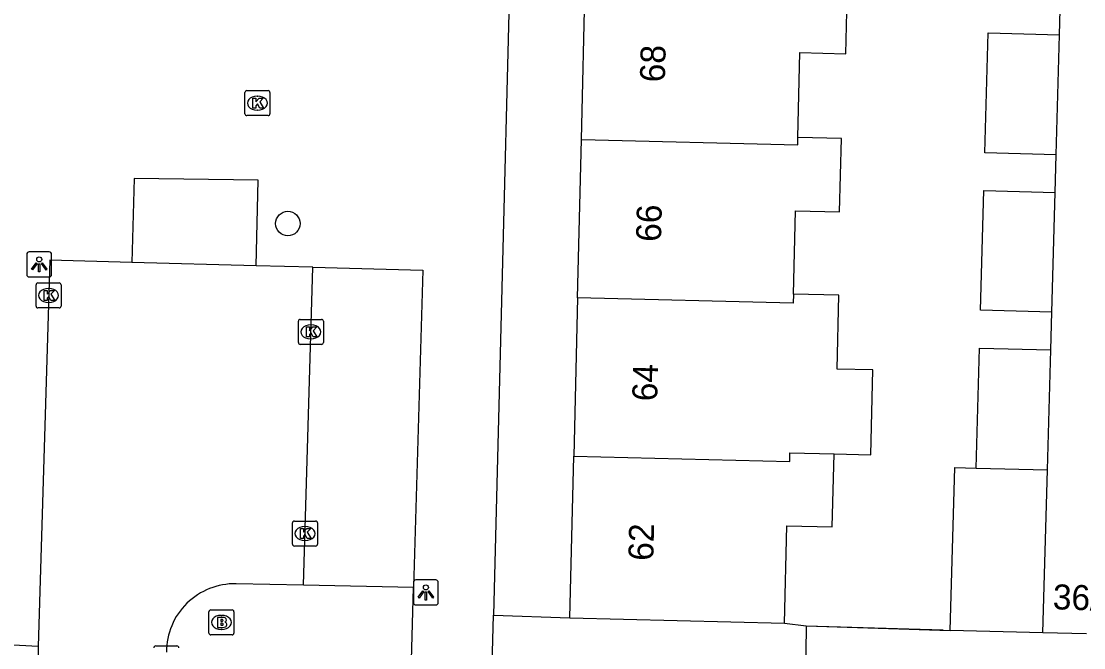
# Model space of a CAD drawing. Extents: x 162082 to 163393, y 388091 to 388632.
# Drawn here: x 162447.32 to 162489.83, y 388250.18 to 388275.23 of the extents above; entities that cross this region are included whole.
import ezdxf

# ---------------------------------------------------------------- set-up
doc = ezdxf.new("R2010")
doc.units = 0
for name, color, linetype in [('IMGEO_Boom', 7, 'Continuous'), ('IMGEO_Brandkraan', 7, 'Continuous'), ('IMGEO_Kolk', 7, 'Continuous'), ('IMGEO_Lichtpunt', 7, 'Continuous'), ('IMGEO_Muur', 7, 'Continuous'), ('IMGEO_Pand', 7, 'Continuous'), ('IMGEO_Pand_nummerreeks', 7, 'Continuous'), ('IMGEO_Rijbaan_lokaal_open', 7, 'Continuous'), ('IMGEO_Voetpad_open', 7, 'Continuous')]:
    doc.layers.add(name, color=color, linetype=linetype)

msp = doc.modelspace()

# ---------------------------------------------------------------- linework, layer by layer
at = {"layer": 'IMGEO_Boom'}
msp.add_circle((162457.99, 388267.141), 0.489, dxfattribs=at)
at = {"layer": 'IMGEO_Brandkraan'}
for p, q in [((162454.832, 388250.766), (162454.832, 388251.618)), ((162454.907, 388251.692), (162455.759, 388251.692)), ((162455.32, 388251.472), (162455.345, 388251.472)), ((162455.833, 388251.618), (162455.833, 388250.766)), ((162455.343, 388250.912), (162455.318, 388250.912)), ((162455.759, 388250.692), (162454.907, 388250.692))]:
    msp.add_line(p, q, dxfattribs=at)
for points in [[(162454.832, 388250.766), (162454.832, 388251.618)], [(162454.907, 388251.692), (162455.759, 388251.692)], [(162455.18, 388251.392), (162455.18, 388250.992), (162455.393, 388250.992)], [(162455.411, 388251.392), (162455.18, 388251.392)], [(162455.833, 388251.618), (162455.833, 388250.766)], [(162455.359, 388251.311), (162455.305, 388251.311), (162455.305, 388251.235)], [(162455.305, 388251.235), (162455.358, 388251.235)], [(162455.367, 388251.159), (162455.305, 388251.159), (162455.305, 388251.078)], [(162455.305, 388251.078), (162455.367, 388251.078)], [(162455.759, 388250.692), (162454.907, 388250.692)]]:
    msp.add_lwpolyline(points, dxfattribs=at)
for centre, radius, start, end in [((162454.909, 388251.616), 0.0765, 91.552, 178.448), ((162454.909, 388251.616), 0.0765, 91.552, 178.448), ((162455.415, 388251.247), 0.145, 59.4692, 91.5367), ((162455.44, 388251.294), 0.0922, 285.5137, 58.1501), ((162455.757, 388251.616), 0.0765, 1.552, 88.448), ((162455.757, 388251.616), 0.0765, 1.552, 88.448), ((162455.36, 388251.273), 0.0379, 267.8285, 90.9355), ((162455.368, 388251.118), 0.0404, 269.8759, 90.5077), ((162455.399, 388251.243), 0.251, 268.6676, 293.5347), ((162455.445, 388251.102), 0.105, 301.3115, 78.989), ((162454.909, 388250.768), 0.0765, 181.552, 268.448), ((162454.909, 388250.768), 0.0765, 181.552, 268.448), ((162455.757, 388250.768), 0.0765, 271.552, 358.448), ((162455.757, 388250.768), 0.0765, 271.552, 358.448)]:
    msp.add_arc(centre, radius, start, end, dxfattribs=at)
for centre, major_axis, ratio, start_param, end_param in [((162455.319, 388251.192), (-0.387, 0.002), 0.722429, 4.712389, 7.853982), ((162455.344, 388251.192), (-0.39, 0.002), 0.717154, 1.570796, 4.712389)]:
    msp.add_ellipse(centre, major_axis=major_axis, ratio=ratio, start_param=start_param, end_param=end_param, dxfattribs=at)
at = {"layer": 'IMGEO_Kolk'}
for p, q in [((162456.271, 388271.532), (162456.271, 388272.384)), ((162456.346, 388272.458), (162457.198, 388272.458)), ((162456.759, 388272.238), (162456.784, 388272.238)), ((162457.272, 388272.384), (162457.272, 388271.532)), ((162457.198, 388271.458), (162456.346, 388271.458)), ((162456.782, 388271.678), (162456.757, 388271.678)), ((162447.917, 388263.84), (162447.917, 388264.692)), ((162447.992, 388264.766), (162448.844, 388264.766)), ((162448.405, 388264.546), (162448.43, 388264.546)), ((162448.918, 388264.692), (162448.918, 388263.84)), ((162448.844, 388263.766), (162447.992, 388263.766)), ((162448.428, 388263.986), (162448.403, 388263.986)), ((162458.41, 388262.382), (162458.41, 388263.234)), ((162458.485, 388263.308), (162459.337, 388263.308)), ((162459.411, 388263.234), (162459.411, 388262.382)), ((162458.898, 388263.088), (162458.923, 388263.088)), ((162458.921, 388262.528), (162458.896, 388262.528)), ((162459.337, 388262.308), (162458.485, 388262.308)), ((162458.175, 388254.318), (162458.175, 388255.17)), ((162458.25, 388255.244), (162459.102, 388255.244)), ((162459.176, 388255.17), (162459.176, 388254.318)), ((162458.663, 388255.024), (162458.688, 388255.024)), ((162458.686, 388254.464), (162458.661, 388254.464)), ((162459.102, 388254.244), (162458.25, 388254.244)), ((162452.703, 388250.251), (162453.555, 388250.251))]:
    msp.add_line(p, q, dxfattribs=at)
for points in [[(162456.271, 388271.532), (162456.271, 388272.384)], [(162456.346, 388272.458), (162457.198, 388272.458)], [(162456.592, 388272.158), (162456.715, 388272.158), (162456.715, 388272.007), (162456.845, 388272.158), (162457.009, 388272.158), (162456.863, 388272.007), (162457.016, 388271.758), (162456.864, 388271.758), (162456.779, 388271.922), (162456.715, 388271.855), (162456.715, 388271.758), (162456.592, 388271.758), (162456.592, 388272.158)], [(162457.272, 388272.384), (162457.272, 388271.532)], [(162457.198, 388271.458), (162456.346, 388271.458)], [(162447.917, 388263.84), (162447.917, 388264.692)], [(162447.992, 388264.766), (162448.844, 388264.766)], [(162448.918, 388264.692), (162448.918, 388263.84)], [(162448.238, 388264.466), (162448.361, 388264.466), (162448.361, 388264.315), (162448.491, 388264.466), (162448.655, 388264.466), (162448.509, 388264.315), (162448.662, 388264.066), (162448.51, 388264.066), (162448.425, 388264.23), (162448.361, 388264.163), (162448.361, 388264.066), (162448.238, 388264.066), (162448.238, 388264.466)], [(162448.844, 388263.766), (162447.992, 388263.766)], [(162458.41, 388262.382), (162458.41, 388263.234)], [(162458.485, 388263.308), (162459.337, 388263.308)], [(162459.411, 388263.234), (162459.411, 388262.382)], [(162458.731, 388263.008), (162458.854, 388263.008), (162458.854, 388262.857), (162458.984, 388263.008), (162459.148, 388263.008), (162459.002, 388262.857), (162459.155, 388262.608), (162459.003, 388262.608), (162458.918, 388262.772), (162458.854, 388262.705), (162458.854, 388262.608), (162458.731, 388262.608), (162458.731, 388263.008)], [(162459.337, 388262.308), (162458.485, 388262.308)], [(162458.175, 388254.318), (162458.175, 388255.17)], [(162458.25, 388255.244), (162459.102, 388255.244)], [(162459.176, 388255.17), (162459.176, 388254.318)], [(162458.496, 388254.944), (162458.619, 388254.944), (162458.619, 388254.793), (162458.749, 388254.944), (162458.913, 388254.944), (162458.767, 388254.793), (162458.92, 388254.544), (162458.768, 388254.544), (162458.683, 388254.708), (162458.619, 388254.641), (162458.619, 388254.544), (162458.496, 388254.544), (162458.496, 388254.944)], [(162459.102, 388254.244), (162458.25, 388254.244)], [(162452.703, 388250.251), (162453.555, 388250.251)]]:
    msp.add_lwpolyline(points, dxfattribs=at)
for centre, start, end in [((162456.348, 388272.382), 91.552, 178.448), ((162456.348, 388272.382), 91.552, 178.448), ((162457.196, 388272.382), 1.552, 88.448), ((162457.196, 388272.382), 1.552, 88.448), ((162456.348, 388271.534), 181.552, 268.448), ((162456.348, 388271.534), 181.552, 268.448), ((162457.196, 388271.534), 271.552, 358.448), ((162457.196, 388271.534), 271.552, 358.448), ((162447.994, 388264.69), 91.552, 178.448), ((162447.994, 388264.69), 91.552, 178.448), ((162448.842, 388264.69), 1.552, 88.448), ((162448.842, 388264.69), 1.552, 88.448), ((162447.994, 388263.842), 181.552, 268.448), ((162447.994, 388263.842), 181.552, 268.448), ((162448.842, 388263.842), 271.552, 358.448), ((162448.842, 388263.842), 271.552, 358.448), ((162458.487, 388263.232), 91.552, 178.448), ((162458.487, 388263.232), 91.552, 178.448), ((162459.335, 388263.232), 1.552, 88.448), ((162459.335, 388263.232), 1.552, 88.448), ((162458.487, 388262.384), 181.552, 268.448), ((162458.487, 388262.384), 181.552, 268.448), ((162459.335, 388262.384), 271.552, 358.448), ((162459.335, 388262.384), 271.552, 358.448), ((162458.252, 388255.168), 91.552, 178.448), ((162458.252, 388255.168), 91.552, 178.448), ((162459.1, 388255.168), 1.552, 88.448), ((162459.1, 388255.168), 1.552, 88.448), ((162458.252, 388254.32), 181.552, 268.448), ((162458.252, 388254.32), 181.552, 268.448), ((162459.1, 388254.32), 271.552, 358.448), ((162459.1, 388254.32), 271.552, 358.448), ((162452.705, 388250.175), 91.552, 178.448), ((162452.705, 388250.175), 91.552, 178.448), ((162453.553, 388250.175), 1.552, 88.448), ((162453.553, 388250.175), 1.552, 88.448)]:
    msp.add_arc(centre, 0.0765, start, end, dxfattribs=at)
for centre, major_axis, ratio, start_param, end_param in [((162456.758, 388271.958), (-0.387, 0.002), 0.722429, 4.712389, 7.853982), ((162456.783, 388271.958), (-0.39, 0.002), 0.717154, 1.570796, 4.712389), ((162448.404, 388264.266), (-0.387, 0.002), 0.722429, 4.712389, 7.853982), ((162448.429, 388264.266), (-0.39, 0.002), 0.717154, 1.570796, 4.712389), ((162458.897, 388262.808), (-0.387, 0.002), 0.722429, 4.712389, 7.853982), ((162458.922, 388262.808), (-0.39, 0.002), 0.717154, 1.570796, 4.712389), ((162458.662, 388254.744), (-0.387, 0.002), 0.722429, 4.712389, 7.853982), ((162458.687, 388254.744), (-0.39, 0.002), 0.717154, 1.570796, 4.712389)]:
    msp.add_ellipse(centre, major_axis=major_axis, ratio=ratio, start_param=start_param, end_param=end_param, dxfattribs=at)
at = {"layer": 'IMGEO_Lichtpunt'}
for p, q in [((162447.543, 388265.91), (162447.543, 388265.103)), ((162447.543, 388265.91), (162447.543, 388265.103)), ((162448.445, 388266.005), (162447.637, 388266.005)), ((162448.445, 388266.005), (162447.637, 388266.005)), ((162448.539, 388265.103), (162448.539, 388265.91)), ((162448.539, 388265.103), (162448.539, 388265.91)), ((162447.637, 388265.009), (162448.445, 388265.009)), ((162447.637, 388265.009), (162448.445, 388265.009)), ((162463.013, 388252.792), (162463.013, 388251.985)), ((162463.013, 388252.792), (162463.013, 388251.985)), ((162463.915, 388252.887), (162463.107, 388252.887)), ((162463.915, 388252.887), (162463.107, 388252.887)), ((162464.009, 388251.985), (162464.009, 388252.792)), ((162464.009, 388251.985), (162464.009, 388252.792)), ((162463.107, 388251.891), (162463.915, 388251.891)), ((162463.107, 388251.891), (162463.915, 388251.891))]:
    msp.add_line(p, q, dxfattribs=at)
for points in [[(162447.917, 388265.574), (162447.956, 388265.546), (162447.768, 388265.284), (162447.73, 388265.311), (162447.917, 388265.574)], [(162448.019, 388265.526), (162448.066, 388265.526), (162448.066, 388265.204), (162448.019, 388265.204), (162448.019, 388265.526)], [(162448.129, 388265.546), (162448.167, 388265.573), (162448.354, 388265.311), (162448.315, 388265.283), (162448.129, 388265.546)], [(162463.387, 388252.456), (162463.426, 388252.428), (162463.238, 388252.166), (162463.2, 388252.193), (162463.387, 388252.456)], [(162463.489, 388252.408), (162463.536, 388252.408), (162463.536, 388252.086), (162463.489, 388252.086), (162463.489, 388252.408)], [(162463.599, 388252.428), (162463.637, 388252.455), (162463.824, 388252.193), (162463.785, 388252.165), (162463.599, 388252.428)]]:
    msp.add_lwpolyline(points, dxfattribs=at)
for centre in [(162448.042, 388265.708), (162463.512, 388252.59)]:
    msp.add_circle(centre, 0.0994, dxfattribs=at)
for centre, start, end in [((162447.637, 388265.91), 90, 180), ((162447.637, 388265.91), 90, 180), ((162448.445, 388265.91), 0, 90), ((162448.445, 388265.91), 0, 90), ((162447.637, 388265.103), 180, 270), ((162447.637, 388265.103), 180, 270), ((162448.445, 388265.103), 270, 0), ((162448.445, 388265.103), 270, 360), ((162463.107, 388252.792), 90, 180), ((162463.107, 388252.792), 90, 180), ((162463.915, 388252.792), 0, 90), ((162463.915, 388252.792), 0, 90), ((162463.107, 388251.985), 180, 270), ((162463.107, 388251.985), 180, 270), ((162463.915, 388251.985), 270, 0), ((162463.915, 388251.985), 270, 360)]:
    msp.add_arc(centre, 0.0946, start, end, dxfattribs=at)
at = {"layer": 'IMGEO_Muur'}
for points in [[(162477.859, 388251.16), (162478.732, 388251.049)], [(162478.732, 388251.049), (162484.208, 388250.888)]]:
    msp.add_lwpolyline(points, dxfattribs=at)
at = {"layer": 'IMGEO_Pand'}
for points in [[(162469.737, 388270.498), (162469.89, 388276.829)], [(162478.396, 388270.582), (162478.478, 388273.976), (162480.318, 388273.931), (162480.386, 388276.746), (162478.573, 388276.789)], [(162488.725, 388269.889), (162485.876, 388269.967), (162486.008, 388274.768), (162488.857, 388274.689)], [(162488.725, 388269.889), (162488.857, 388274.689)], [(162469.584, 388264.166), (162469.737, 388270.498)], [(162469.737, 388270.498), (162478.389, 388270.288), (162478.396, 388270.582)], [(162478.221, 388264.316), (162478.301, 388267.654), (162480.064, 388267.611), (162480.135, 388270.54), (162478.396, 388270.582)], [(162488.552, 388263.594), (162485.703, 388263.672), (162485.835, 388268.46), (162488.683, 388268.382)], [(162488.552, 388263.594), (162488.683, 388268.382)], [(162469.584, 388264.166), (162469.431, 388257.835)], [(162478.221, 388264.316), (162478.212, 388263.957), (162469.584, 388264.166)], [(162479.841, 388257.931), (162481.31, 388257.896), (162481.392, 388261.288), (162479.967, 388261.323), (162480.038, 388264.272), (162478.221, 388264.316)], [(162485.529, 388257.362), (162485.661, 388262.164), (162488.51, 388262.086)], [(162488.378, 388257.291), (162488.51, 388262.086)], [(162469.275, 388251.368), (162469.431, 388257.835)], [(162469.431, 388257.835), (162478.07, 388257.626), (162478.078, 388257.973), (162479.841, 388257.931)], [(162477.859, 388251.16), (162477.953, 388255.051), (162479.771, 388255.007), (162479.841, 388257.931)], [(162484.49, 388250.866), (162484.669, 388257.384), (162485.529, 388257.362)], [(162485.529, 388257.362), (162488.378, 388257.291)], [(162488.199, 388250.773), (162488.378, 388257.291)], [(162469.275, 388251.368), (162477.859, 388251.16)], [(162488.199, 388250.773), (162484.49, 388250.866)]]:
    msp.add_lwpolyline(points, dxfattribs=at)
at = {"layer": 'IMGEO_Rijbaan_lokaal_open'}
for points in [[(162451.743, 388265.583), (162448.461, 388265.67), (162448.003, 388250.23)], [(162456.719, 388265.451), (162451.743, 388265.583)], [(162458.985, 388265.391), (162456.719, 388265.451)], [(162458.615, 388252.676), (162458.985, 388265.391)], [(162458.615, 388252.676), (162455.92, 388252.734)], [(162478.732, 388251.049), (162478.71, 388250), (162478.694, 388249.226)], [(162478.732, 388251.049), (162484.49, 388250.866)], [(162489.936, 388250.727), (162488.199, 388250.773)], [(162448.003, 388250.23), (162446.258, 388250.316)], [(162448.003, 388250.23), (162447.965, 388242.951)]]:
    msp.add_lwpolyline(points, dxfattribs=at)
msp.add_arc((162455.862, 388250.006), 2.729, 88.7761, 180.1239, dxfattribs=at)
at = {"layer": 'IMGEO_Voetpad_open'}
for points in [[(162470.199, 388289.627), (162467.19, 388289.696), (162466.216, 388251.474)], [(162488.857, 388274.689), (162488.899, 388276.206)], [(162488.683, 388268.382), (162488.725, 388269.889)], [(162456.719, 388265.451), (162456.804, 388268.874), (162451.836, 388268.944), (162451.743, 388265.583)], [(162458.985, 388265.391), (162463.397, 388265.274), (162463.022, 388252.581)], [(162488.51, 388262.086), (162488.552, 388263.594)], [(162463.022, 388252.581), (162458.615, 388252.676)], [(162462.936, 388249.686), (162463.022, 388252.581)], [(162466.168, 388249.592), (162466.178, 388250), (162466.216, 388251.474)], [(162466.216, 388251.474), (162469.275, 388251.368)], [(162477.859, 388251.16), (162478.732, 388251.049)]]:
    msp.add_lwpolyline(points, dxfattribs=at)

# ---------------------------------------------------------------- texts
at = {"layer": 'IMGEO_Pand_nummerreeks'}
for s, rotation, p in [('68', 88.6165, (162473.073, 388272.783)), ('66', 88.6165, (162472.918, 388266.403)), ('64', 88.6137, (162472.765, 388260.027)), ('62', 88.6165, (162472.61, 388253.647)), ('36/G07', 358.3091, (162488.585, 388251.717))]:
    msp.add_text(s, height=1, rotation=rotation, dxfattribs=at).set_placement(p)

doc.saveas('drawing.dxf')
